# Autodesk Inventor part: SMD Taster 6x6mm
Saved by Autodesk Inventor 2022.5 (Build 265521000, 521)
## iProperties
Created: 2024-12
Part Number: SMD Taster 6x6mm
Material: Generic
Document SubType Name: Modeling
Designer: AdminForWorker
Density: 1 g/cm^3
Appearance: Default
Title: SMD Taster 6x6mm
Author: AdminForWorker
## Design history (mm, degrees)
feature "Body1"
body "Solid1"
